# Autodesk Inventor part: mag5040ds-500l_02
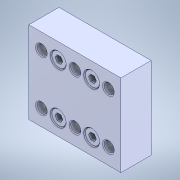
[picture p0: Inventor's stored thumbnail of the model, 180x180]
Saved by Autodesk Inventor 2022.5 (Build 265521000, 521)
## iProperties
Created: 2023-04
Part Number: mag5040ds-500l_02
Material: Generic
Document SubType Name: Modeling
Designer: ImaoCorp
Density: 1 g/cm^3
Appearance: Default
Author: ImaoCorp
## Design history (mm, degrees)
feature "mag5040ds-500l_02"
node "ソリッド1"
